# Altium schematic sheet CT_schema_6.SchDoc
size 390 x 355 mm
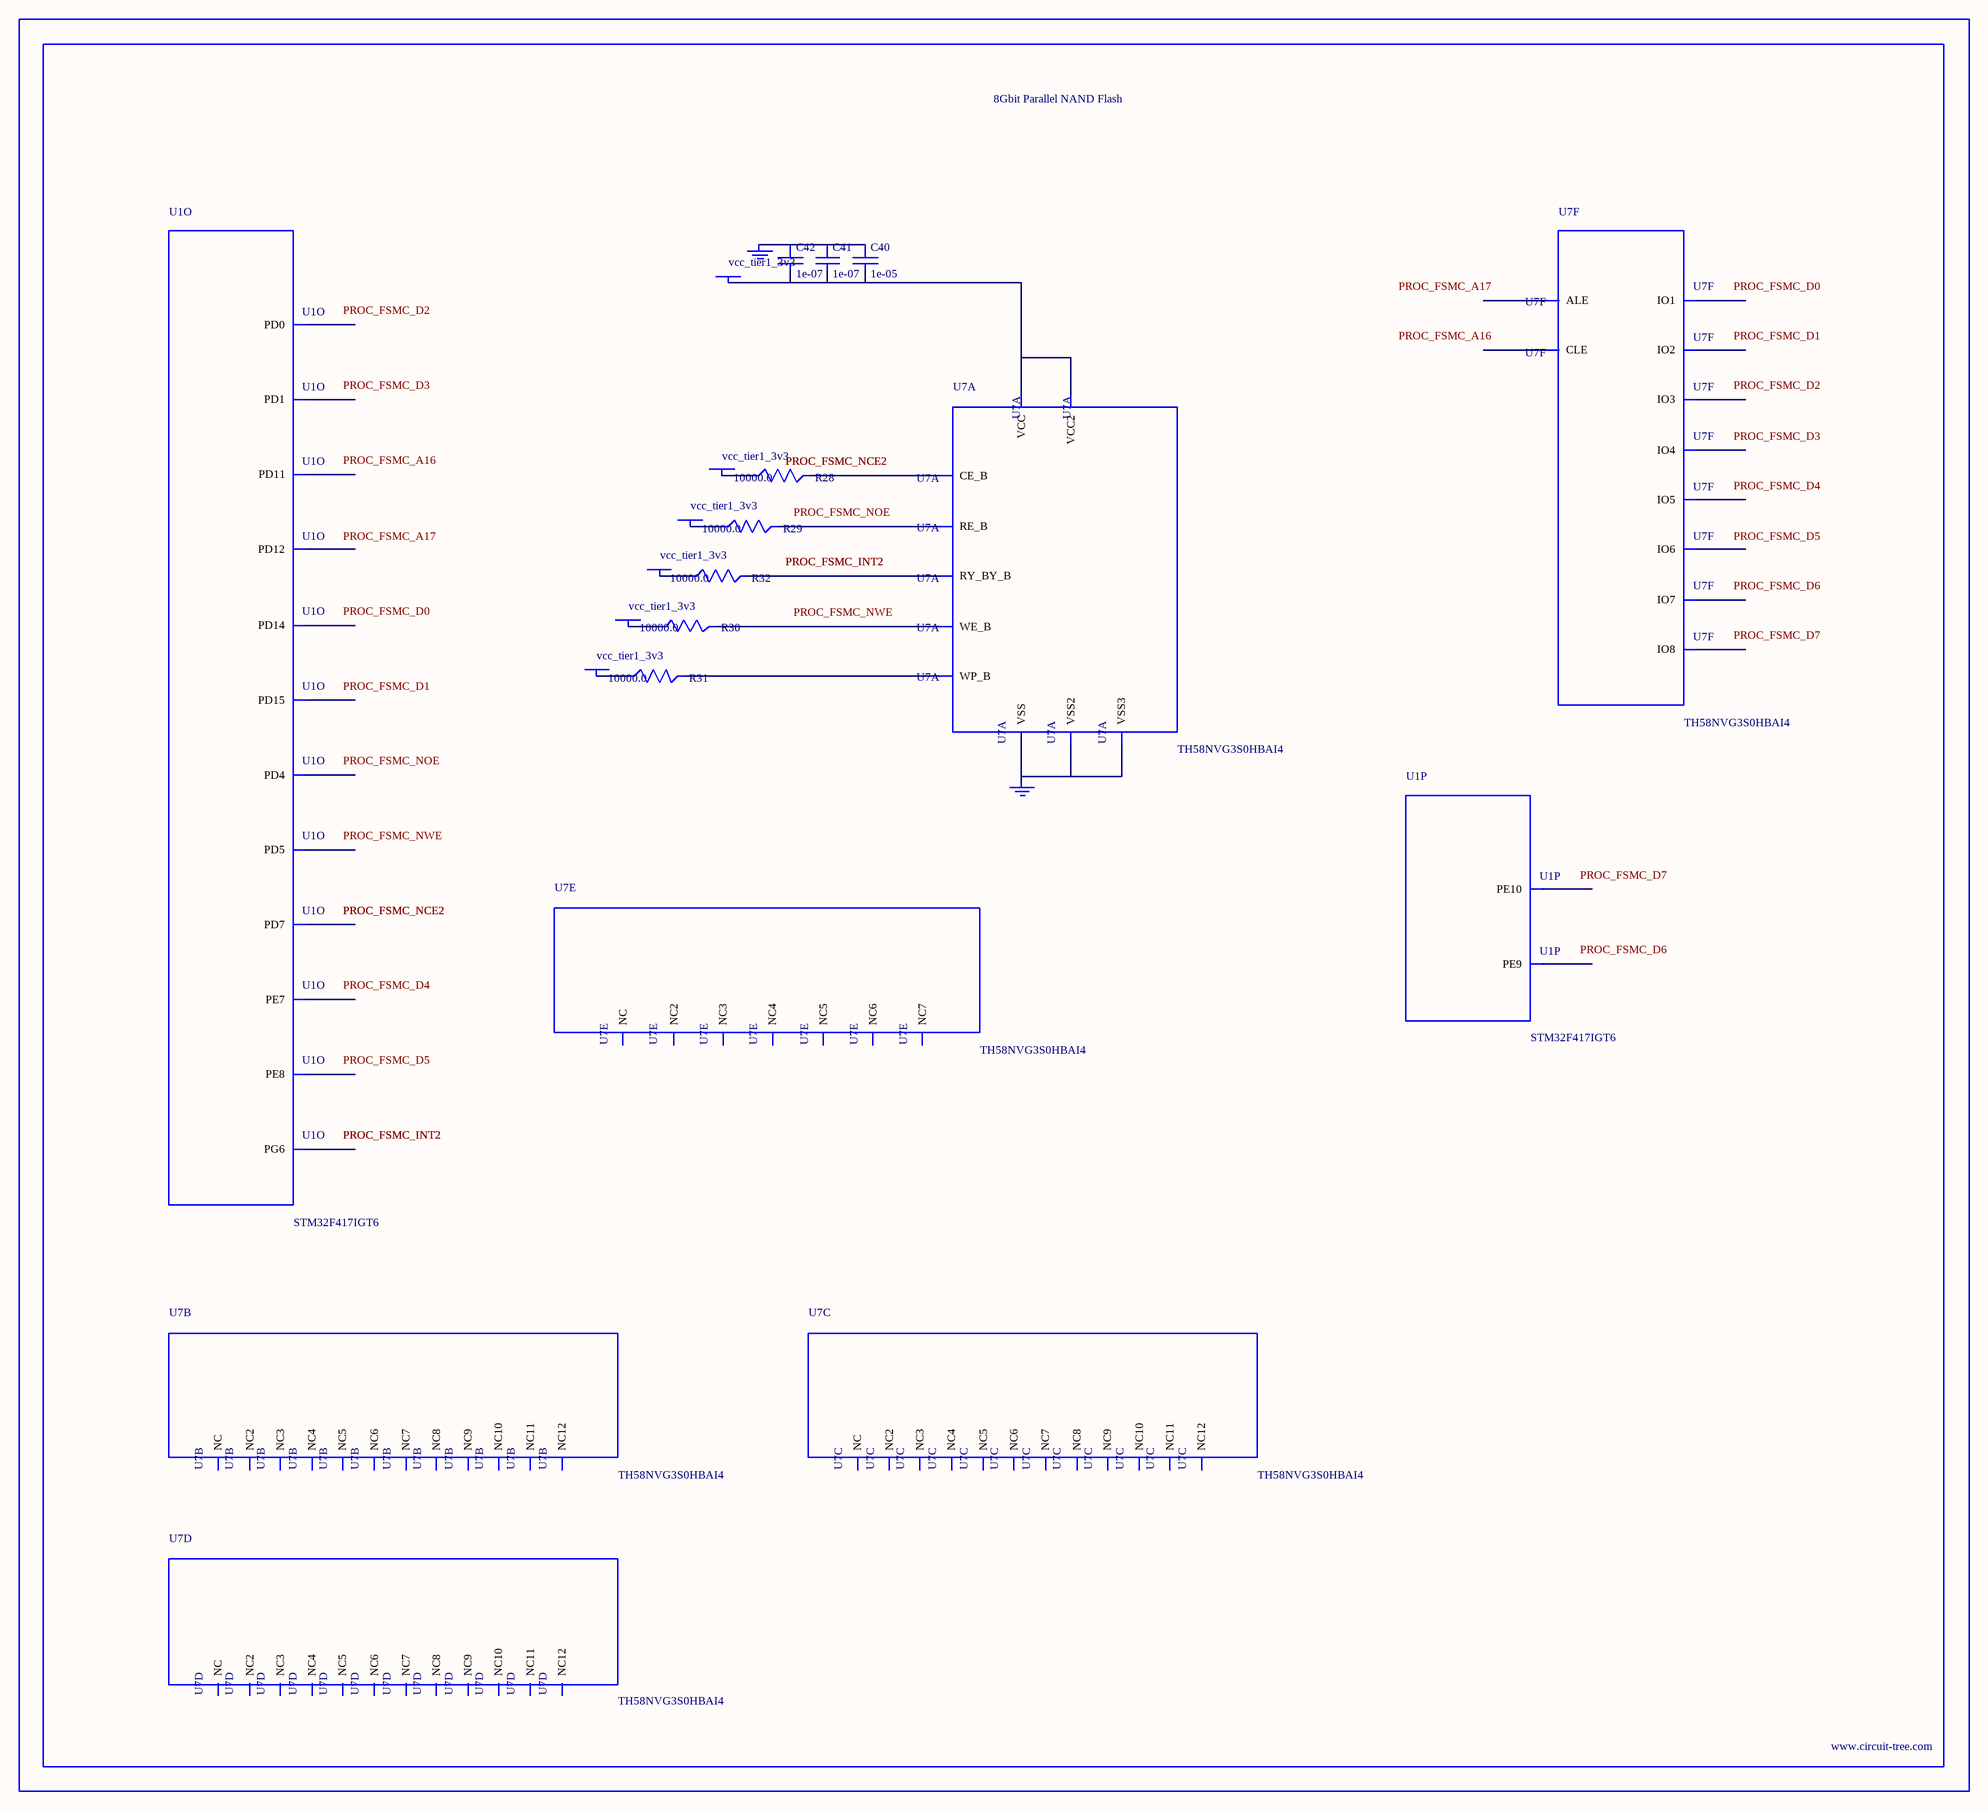
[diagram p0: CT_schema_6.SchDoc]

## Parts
BORDER5  (no value)
C40  1e-05  [C0805]
C41  1e-07  [C0402]
C42  1e-07  [C0402]
GND_INSTANCE_5_0  (no value)
GND_INSTANCE_5_1  (no value)
POWER_INSTANCE_5_0  vcc_tier1_3v3
POWER_INSTANCE_5_1  vcc_tier1_3v3
POWER_INSTANCE_5_2  vcc_tier1_3v3
POWER_INSTANCE_5_3  vcc_tier1_3v3
POWER_INSTANCE_5_4  vcc_tier1_3v3
POWER_INSTANCE_5_5  vcc_tier1_3v3
R28  10000.0  [R0603]
R29  10000.0  [R0603]
R30  10000.0  [R0603]
R31  10000.0  [R0603]
R32  10000.0  [R0603]
U1  STM32F417IGT6  [LQFP176]  (parts O,P of 16)
U7  TH58NVG3S0HBAI4  [TH58NVG3S0HBAI4]  (parts A,B,C,D,E,F of 6)

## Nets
NetC40_1: C40.1 C41.1 C42.1 GND_INSTANCE_5_0.0(GND)
NetC40_2: C40.2 C41.2 C42.2 POWER_INSTANCE_5_5.0(PWR) U7.H8(VCC) U7.J6(VCC2)
NetGND_INSTANCE_5_1_0: GND_INSTANCE_5_1.0(GND) U7.C5(VSS) U7.K3(VSS2) U7.K8(VSS3)
NetPOWER_INSTANCE_5_0_0: POWER_INSTANCE_5_0.0(PWR) R28.1
NetPOWER_INSTANCE_5_1_0: POWER_INSTANCE_5_1.0(PWR) R29.1
NetPOWER_INSTANCE_5_2_0: POWER_INSTANCE_5_2.0(PWR) R30.1
NetPOWER_INSTANCE_5_3_0: POWER_INSTANCE_5_3.0(PWR) R31.1
NetPOWER_INSTANCE_5_4_0: POWER_INSTANCE_5_4.0(PWR) R32.1
NetR28_2: R28.2 U7.C6(CE_B)
NetR29_2: R29.2 U7.D4(RE_B)
NetR30_2: R30.2 U7.C7(WE_B)
NetR31_2: R31.2 U7.C3(WP_B)
NetR32_2: R32.2 U7.C8(RY_BY_B)

Not connected (* = marked no-connect by the designer): U1 68(PE7) 69(PE8) 70(PE9) 73(PE10) 99(PD11) 100(PD12) 104(PD14) 105(PD15) 110(PG6) 142(PD0) 143(PD1) 146(PD4) 147(PD5) 151(PD7); U7 A1(NC) A2(NC3) A9(NC4) A10(NC2) B1(NC5) B9(NC7) B10(NC6) C4(ALE) D3(NC8) D5(CLE) D6(NC9) D7(NC10) D8(NC11) E3(NC12) E4(NC) E5(NC2) E6(NC3) E7(NC4) E8(NC5) F3(NC6) F4(NC7) F5(NC8) F6(NC9) F7(NC10) F8(NC11) G3(NC12) G4(NC) G5(NC2) G6(NC3) G7(NC4) G8(NC5) H3(NC6) H4(IO1) H5(NC7) H6(NC8) H7(NC9) J3(NC10) J4(IO2) J5(NC11) J7(IO6) J8(IO8) K4(IO3) K5(IO4) K6(IO5) K7(IO7) L1(NC12) L2(NC2) L9(NC3) L10(NC) M1(NC4) M2(NC6) M9(NC7) M10(NC5)

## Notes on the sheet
- Labels drawn without touching a wire or pin: PROC_FSMC_A16, PROC_FSMC_A17, PROC_FSMC_D0, PROC_FSMC_D1, PROC_FSMC_D2, PROC_FSMC_D3, PROC_FSMC_D4, PROC_FSMC_D5, PROC_FSMC_D6, PROC_FSMC_D7, PROC_FSMC_NOE, PROC_FSMC_NWE

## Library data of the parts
BORDER5 = BORDER_PAGE5
C40 = C0805C106K8RACTU
C41 C42 = C0402C104K3RACTU
GND_INSTANCE_5_0 GND_INSTANCE_5_1 = GND
POWER_INSTANCE_5_0-POWER_INSTANCE_5_5 = PWR
R28-R32 = RC0603JR-0710KL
